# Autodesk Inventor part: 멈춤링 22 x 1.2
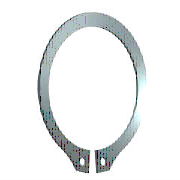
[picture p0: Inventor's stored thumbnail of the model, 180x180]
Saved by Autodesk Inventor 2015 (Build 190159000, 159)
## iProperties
IsCustomPart: 0
Created: 2015-11
Part Number: 멈춤링 22 x 1.2
Material: 스테인리스강
Description: 리테이닝 링(C형)
Document SubType Name: Modeling
Standard: KS B 1336
Designer: mdu
Standards Organization: KS
Language: ko-KR
Size Designation: 22 x 1.2
Categories: <MemberInstance><Categories><Category DisplayName="샤프트 부품" InternalName="7f7aeb1f-a693-4053-b835-cee3144e0d98" Mnemonic="SHFT"><Category DisplayName="써클립" Inter
Density: 8.08 g/cm^3
Appearance: 반광택
Mass: 1.87978 g
Surface Area: 5.91219 cm^2
Volume: 0.232646 cm^3
Author: mdu
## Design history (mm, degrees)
sketch "스케치1"
  geometry: L1 (-6, 0)-(6, 0) reference; L2 (0, 20.189)-(0, -80.536) reference; L3 (-48.09, 0)-(48.09, 0) reference; L4 (-0.5, -21.488)-(-0.5, -25.588); L5 (-0.5, -6.54)-(-0.5, -13.29); L6 (-2.795, 2.7)-(3.672, 2.7); L7 (0.5, -6.54)-(0.5, -13.29); L8 (0.5, -21.488)-(0.5, -25.588); C1 r 1 at (-2, -23.437); C2 r 1 at (2, -23.437); A1 r 10.5 centre (0, -11) between (0.5, -21.488) and (-0.5, -21.488); A2 r 13.025 centre (0, -10.325) between (5.149, -22.289) and (-5.149, -22.289); A3 r 14.597 centre (0, -11) between (-2.318, -25.411) and (-0.5, -25.588); A4 r 2 centre (-2, -23.437) between (-3.97, -23.781) and (-2.318, -25.411); A5 r 2 centre (-5.94, -24.126) between (-3.97, -23.781) and (-5.149, -22.289); A6 r 2 centre (5.94, -24.126) between (5.149, -22.289) and (3.97, -23.781); A7 r 2 centre (2, -23.437) between (2.318, -25.411) and (3.97, -23.781); A8 r 14.597 centre (0, -11) between (0.5, -25.588) and (2.318, -25.411)
  constraints: 16 point on circle, 12 end point, 10 centre point, 9 symmetric about line, 5 point on line, 4 tangent, 3 coincident, 2 horizontal, 1 perpendicular, 1 vertical, 5 other
  dimensions: "d0" = 21 diameter of A1 (= ND); "d1" = 4.1 distance of L4.end L4.start (= SRB2); "d6" = 0.5 distance between parallel lines of L2 L5 (= 0.25 x SD5); "d7" = 2.7 distance between parallel lines of L6 L3 (= SRB1); "d8" = 0.675 distance of A1.centre A2.centre (= 0.25 x SRB1); "d9" = 2 radius of A4 (= SD5); "d10" = 2 radius of A5 (= SD5); "d11" = 1.5 distance from line of L4 A4.centre (= 0.75 x SD5); "d12" = 2 diameter of C1 (= SD5); "d13" = 2 diameter of C2 (= SD5); "d14" = 11 distance from line of A1.centre L1 (= 0.5 x WD)
extrude "본체" new body sketch "스케치1" distance "d2" = 1.2 (= SD); taper "d3" = 0 deg
workaxis "Work Axis1"
workplane "Work Plane1"
body "Solid1"
other parameters: "WD" = 22 (= WDMIN) [user parameter; used in 1 equation term], "SD" = 1.2 [user parameter; used in 1 equation term], "SRB1" = 2.7 [user parameter; used in 2 equation terms], "ND" = 21 [user parameter; used in 1 equation term], "SRB2" = 4.1 [user parameter; used in 1 equation term], "SD5" = 2 [user parameter; used in 6 equation terms], "d15" = 0, "d16" = 0, "d17" = 0, "d41" = 0, "d42" = 0, "WDMIN" = 22 [user parameter; used in 1 equation term], "SD3" = 20.5 [user parameter], "WDMAX" = 24 [user parameter]
